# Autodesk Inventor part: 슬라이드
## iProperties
Company: 한국ATC센터
Created: 2014-11
Part Number: 슬라이드
Document SubType Name: Modeling
Designer: KYOUNG IL JANG
Density: 7.86 g/cm^3
Material: 강, 연강
Mass: 436.103 g
Surface Area: 105.764 cm^2
Volume: 55.4838 cm^3
Author: KYOUNG IL JANG
